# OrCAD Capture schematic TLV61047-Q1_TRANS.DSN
size A
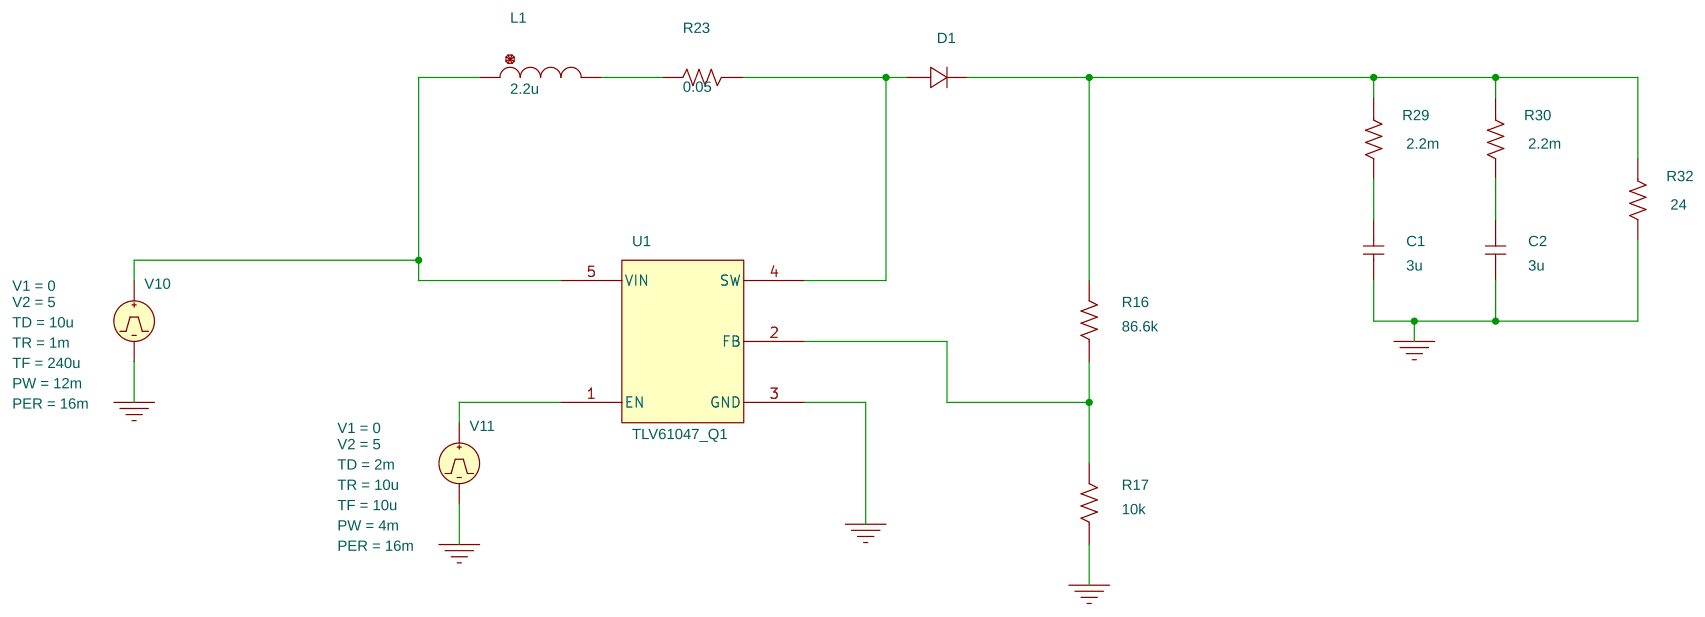
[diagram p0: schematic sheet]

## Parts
C1  3u  [cap196]
C2  3u  [cap196]
D1  Dbreak
L1  2.2u  [DISC350x175LS200x100034]
R16  86.6k  [AX/RC05]
R17  10k  [AX/RC05]
R23  0.05  [AX/RC05]
R29  2.2m  [AX/RC05]
R30  2.2m  [AX/RC05]
R32  24  [AX/RC05]
U1  TLV61047_Q1
V10  VPULSE
V11  VPULSE

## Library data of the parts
C1 C2 = C
D1 = Dbreak
L1 = L
R16 R17 R23 R29 R30 R32 = R
U1 = TLV61047_Q1
V10 = VPULSE: PER: 16m; PW: 12m; TD: 10u; TF: 240u; TR: 1m; V1: 0; V2: 5
V11 = VPULSE: PER: 16m; PW: 4m; TD: 2m; TF: 10u; TR: 10u; V1: 0; V2: 5

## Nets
0: C1.1 C2.1 R17.1 R32.2 U1.3(GND) V10.2(-) V11.2(-)
N54409: L1.1 U1.5(VIN) V10.1(+)
N54417: L1.2 R23.2
N54423: D1.0(1) R23.1 U1.4(SW)
N54437: D1.1(2) R16.2 R29.1 R30.1 R32.1
N54515: C1.2 R29.2
N54521: C2.2 R30.2
N54705: R16.1 R17.2 U1.2(FB)
N54741: U1.1(EN) V11.1(+)
